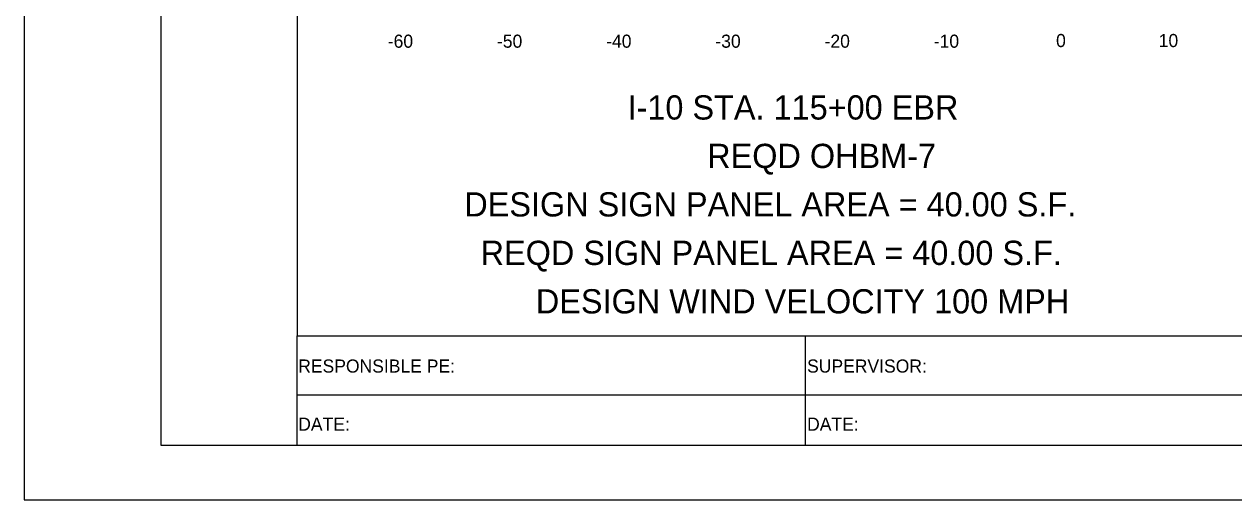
# Model space of a CAD drawing. Extents: x 1797809 to 2198143, y 249608 to 1237864.
# Drawn here: x 2195203.8 to 2195314.6, y 1237118 to 1237161.6 of the extents above; entities that cross this region are included whole.
import ezdxf

# ---------------------------------------------------------------- set-up
doc = ezdxf.new("R2010")
doc.units = 0
for name, color, linetype in [('10', 7, 'Continuous'), ('GSCOLORFILL', 7, 'Continuous'), ('GSOUTLINE', 7, 'Continuous'), ('GSSHT', 7, 'Continuous'), ('Level 45', 7, 'Continuous'), ('Level 55', 7, 'Continuous')]:
    doc.layers.add(name, color=color, linetype=linetype)

msp = doc.modelspace()

# ---------------------------------------------------------------- linework, layer by layer
at = {"layer": 'GSCOLORFILL'}
for p, q in [((2195228.78, 1237123.04), (2195228.78, 1237133.05)), ((2195275.31, 1237133.05), (2195275.31, 1237123.04)), ((2195228.78, 1237127.65), (2195384.41, 1237127.65))]:
    msp.add_line(p, q, dxfattribs=at)
msp.add_lwpolyline([(2195216.29, 1237123.04), (2195538.79, 1237123.04), (2195538.79, 1237333.04), (2195216.29, 1237333.04)], close=True, dxfattribs=at)
at = {"layer": 'GSSHT'}
msp.add_lwpolyline([(2195203.79, 1237118.04), (2195543.79, 1237118.04), (2195543.79, 1237338.04), (2195203.79, 1237338.04)], close=True, dxfattribs=at)
at = {"layer": 'Level 45'}
msp.add_lwpolyline([(2195228.78, 1237133.05), (2195528.78, 1237133.05), (2195528.78, 1237323.05), (2195228.78, 1237323.05)], close=True, dxfattribs=at)

# ---------------------------------------------------------------- texts
at = {"layer": '10'}
for s, p in [('-60', (2195237.08, 1237159.45)), ('-50', (2195247.08, 1237159.45)), ('-40', (2195257.08, 1237159.45)), ('-30', (2195267.08, 1237159.45)), ('-20', (2195277.08, 1237159.45)), ('-10', (2195287.08, 1237159.45)), ('0', (2195298.28, 1237159.51)), ('10', (2195307.68, 1237159.51))]:
    msp.add_text(s, height=1.2, dxfattribs=at).set_placement(p)
at = {"layer": 'GSOUTLINE'}
for s, p in [('RESPONSIBLE PE:', (2195228.88, 1237129.69)), ('SUPERVISOR:', (2195275.48, 1237129.69)), ('DATE:', (2195228.88, 1237124.37)), ('DATE:', (2195275.48, 1237124.37))]:
    msp.add_text(s, height=1.2, rotation=360, dxfattribs=at).set_placement(p)
at = {"layer": 'Level 55'}
for s, p in [('I-10 STA. 115+00 EBR', (2195259.04, 1237152.87)), ('REQD OHBM-7', (2195266.33, 1237148.43)), ('DESIGN SIGN PANEL AREA = 40.00 S.F.', (2195244.09, 1237143.99)), ('REQD SIGN PANEL AREA = 40.00 S.F.', (2195245.58, 1237139.55)), ('DESIGN WIND VELOCITY 100 MPH', (2195250.64, 1237135.11))]:
    msp.add_text(s, height=2.2209, dxfattribs=at).set_placement(p)

doc.saveas('drawing.dxf')
